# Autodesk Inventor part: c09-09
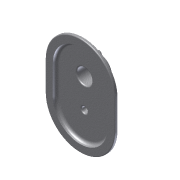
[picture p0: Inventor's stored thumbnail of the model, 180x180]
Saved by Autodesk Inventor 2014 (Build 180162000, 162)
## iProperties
Created: 2010-12
Part Number: c09-09
Document SubType Name: Modeling
Designer: Thom Tremblay
Density: 7.25 g/cm^3
Material: Iron, Cast
Mass: 515.624 g
Surface Area: 438.513 cm^2
Volume: 71.1205 cm^3
Appearance: Aluminum Cast
Author: Thom Tremblay
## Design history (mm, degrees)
sketch "Sketch1"
  geometry: L1 (-50, -50)-(-50, 0); L2 (50, 0)-(50, -50); L3 (-60, 0)-(-60, -50); L4 (60, -50)-(60, 0); A1 r 50 centre (0, 0) between (50, 0) and (-50, 0); A2 r 50 centre (0, -50) between (-50, -50) and (50, -50); A3 r 60 centre (0, -50) between (-60, -50) and (60, -50); A4 r 60 centre (0, 0) between (60, 0) and (-60, 0); 1 further point
  constraints: 8 end point, 8 point on circle, 4 centre point, 4 tangent, 2 parallel, 1 coincident, 1 vertical, 3 other
  dimensions: "d0" = 50 distance of L2.start L2.end; "d1" = 50 radius of A1; "d2" = 10 radial gap between concentric circles of A4 A1
extrude "Extrusion1" new body sketch "Sketch1" distance "d3" = 10; taper "d4" = -2 deg
fillet "Fillet1" dims "d7" = 8
shell "Shell3" dims "d142" = 3
extrude "Extrusion2" join sketch "Sketch1" distance "d5" = 5; taper "d6" = -2 deg
fillet "Fillet2" dims "d9" = 1.5, "d10" = 1
sketch "Sketch7"
  geometry: C1 r 22.5 at (0, 0); 1 further point
  constraints: 1 centre point, 1 coincident
  dimensions: "d63" = 45 diameter of C1
extrude "Extrusion8" join sketch "Sketch7" distance "d64" = 24; taper "d65" = -2 deg
fillet "Fillet11" dims "d75" = 3
sketch "Sketch8"
  geometry: C1 r 12.5 at (0, -50); A1 r 60 centre (0, -50) between (-60, -50) and (60, -50) reference; 1 further point
  constraints: 1 centre point, 1 coincident
  dimensions: "d76" = 25 diameter of C1
extrude "Extrusion9" join sketch "Sketch8" distance "d77" = 12; taper "d78" = -2 deg; dims "d89" = 8, "d90" = -2 deg
fillet "Fillet12" dims "d79" = 3
sketch "Sketch9" dims "d91" = 45
  geometry: L1 (0, 0)-(0, 22.5); C1 r 4 at (0, 22.5); 1 further point
  constraints: 2 end point, 1 centre point, 1 coincident, 1 vertical, 1 vertical alignment, 2 other
  dimensions: "d92" = 8 diameter of C1
extrude "Extrusion10" join sketch "Sketch9" stored distance "d95" = 0; taper "d96" = 2 deg
sketch "Sketch12"
  geometry: C1 r 5 at (0, 0); A1 r 41.925 centre (0, 0) between (-41.925, 0) and (41.925, 0) reference
  constraints: 1 centre point, 1 coincident
  dimensions: "d136" = 10 diameter of C1
extrude "Extrusion11" cut sketch "Sketch12" distance "d137" = 8; taper "d138" = -2 deg
fillet "Fillet13" dims "d97" = 3
pattern_circular "Circular Pattern2" dims angle "d133" = 360 deg
sketch "Sketch13"
  geometry: C1 r 13 at (0, 50); A1 r 41.925 centre (0, 50) between (41.925, 50) and (-41.925, 50) reference
  constraints: 1 centre point, 1 coincident
  dimensions: "d139" = 26 diameter of C1
extrude "Extrusion12" cut sketch "Sketch13" stored distance "d140" = 10; taper "d141" = 2 deg
fillet "Fillet14" dims "d135" = 2
fillet "Fillet15" dims "d143" = 2
body "Solid1"
